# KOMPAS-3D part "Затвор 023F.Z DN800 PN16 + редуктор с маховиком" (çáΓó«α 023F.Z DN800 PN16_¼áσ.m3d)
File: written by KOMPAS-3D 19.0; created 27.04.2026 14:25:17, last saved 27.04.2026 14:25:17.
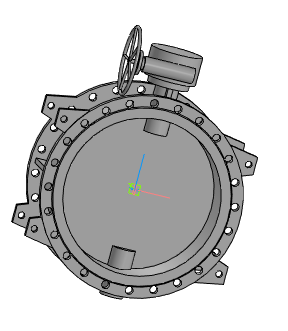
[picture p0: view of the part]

Document properties: Полное имя файла: ..\..\Затвор 023F.Z DN200-DN1600_с маховиком\Затвор 023F.Z DN800 PN16 + редуктор с маховиком.a3d

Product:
- Part/product: Затвор 023F.Z DN800 PN16 + редуктор с маховиком
    Масса: 785.977

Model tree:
1. Операция без истории:1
